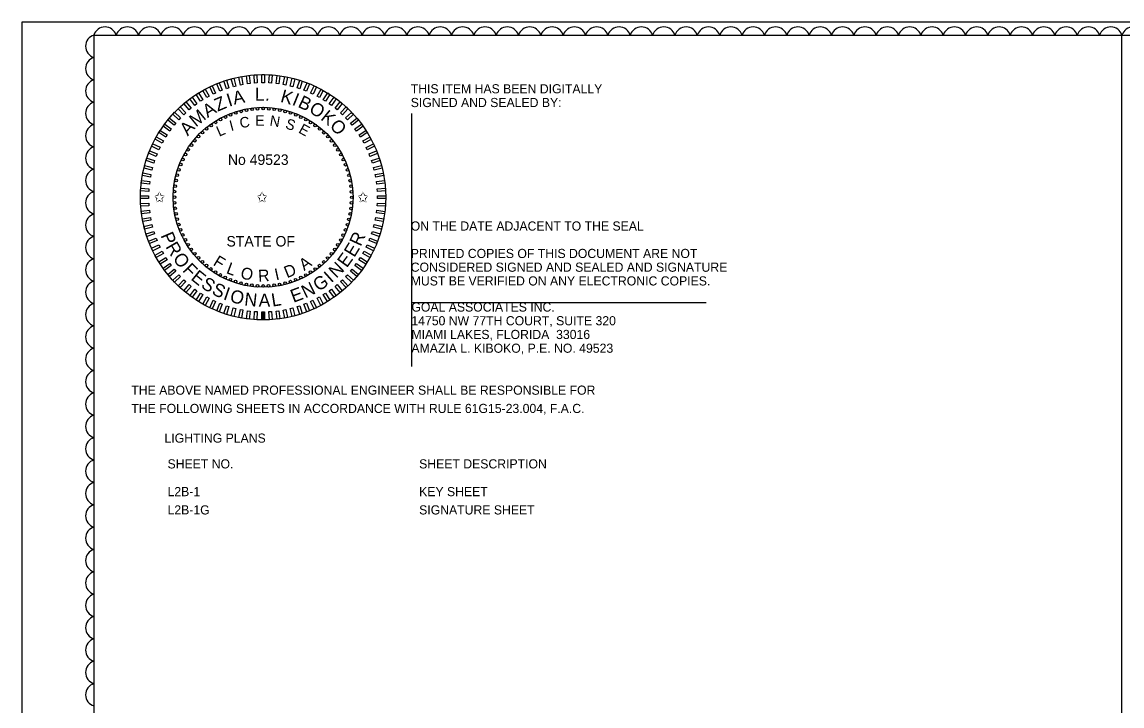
# Model space of a CAD drawing. Extents: x -816.9 to -790.1, y -2199.5 to -2188.9.
# Drawn here: x -811.34 to -802.91, y -2194.13 to -2188.9 of the extents above; entities that cross this region are included whole.
import ezdxf

# ---------------------------------------------------------------- set-up
doc = ezdxf.new("R2010")
doc.units = 0
for name, color, linetype in [('Cloud_dp', 7, 'Continuous'), ('Logo_dp', 7, 'Continuous'), ('NonPlottingEle_dp', 7, 'Continuous'), ('PlotBorder_dp', 7, 'Continuous'), ('ScratchEle_dp', 7, 'Continuous'), ('SheetBorder_dp', 7, 'Continuous'), ('TextMisc', 7, 'Continuous'), ('TextNotes', 7, 'Continuous')]:
    doc.layers.add(name, color=color, linetype=linetype)

msp = doc.modelspace()

# ---------------------------------------------------------------- linework, layer by layer
at = {"layer": 'Cloud_dp'}
for centre, start, end in [((-810.7002, -2189.0276), 17.5, 162.5), ((-810.5291, -2189.0276), 17.5, 162.5), ((-810.358, -2189.0276), 17.5, 162.5), ((-810.1868, -2189.0276), 17.5, 162.5), ((-810.0157, -2189.0276), 17.5, 162.5), ((-809.8446, -2189.0276), 17.5, 162.5), ((-809.6735, -2189.0276), 17.5, 162.5), ((-809.5024, -2189.0276), 17.5, 162.5), ((-809.3312, -2189.0276), 17.5, 162.5), ((-809.1601, -2189.0276), 17.5, 162.5), ((-808.989, -2189.0276), 17.5, 162.5), ((-808.8179, -2189.0276), 17.5, 162.5), ((-808.6467, -2189.0276), 17.5, 162.5), ((-808.4756, -2189.0276), 17.5, 162.5), ((-808.3045, -2189.0276), 17.5, 162.5), ((-808.1334, -2189.0276), 17.5, 162.5), ((-807.9622, -2189.0276), 17.5, 162.5), ((-807.7911, -2189.0276), 17.5, 162.5), ((-807.62, -2189.0276), 17.5, 162.5), ((-807.4489, -2189.0276), 17.5, 162.5), ((-807.2778, -2189.0276), 17.5, 162.5), ((-807.1066, -2189.0276), 17.5, 162.5), ((-806.9355, -2189.0276), 17.5, 162.5), ((-806.7644, -2189.0276), 17.5, 162.5), ((-806.5933, -2189.0276), 17.5, 162.5), ((-806.4221, -2189.0276), 17.5, 162.5), ((-806.251, -2189.0276), 17.5, 162.5), ((-806.0799, -2189.0276), 17.5, 162.5), ((-805.9088, -2189.0276), 17.5, 162.5), ((-805.7377, -2189.0276), 17.5, 162.5), ((-805.5665, -2189.0276), 17.5, 162.5), ((-805.3954, -2189.0276), 17.5, 162.5), ((-805.2243, -2189.0276), 17.5, 162.5), ((-805.0532, -2189.0276), 17.5, 162.5), ((-804.882, -2189.0276), 17.5, 162.5), ((-804.7109, -2189.0276), 17.5, 162.5), ((-804.5398, -2189.0276), 17.5, 162.5), ((-804.3687, -2189.0276), 17.5, 162.5), ((-804.1976, -2189.0276), 17.5, 162.5), ((-804.0264, -2189.0276), 17.5, 162.5), ((-803.8553, -2189.0276), 17.5, 162.5), ((-803.6842, -2189.0276), 17.5, 162.5), ((-803.5131, -2189.0276), 17.5, 162.5), ((-803.3419, -2189.0276), 17.5, 162.5), ((-803.1708, -2189.0276), 17.5, 162.5), ((-802.9997, -2189.0276), 17.5, 162.5), ((-802.8286, -2189.0276), 17.5, 162.5), ((-810.7588, -2189.0862), 107.5, 252.5), ((-810.7588, -2189.2573), 107.5, 252.5), ((-810.7588, -2189.4284), 107.5, 252.5), ((-810.7588, -2189.5996), 107.5, 252.5), ((-810.7588, -2189.7707), 107.5, 252.5), ((-810.7588, -2189.9418), 107.5, 252.5), ((-810.7588, -2190.1129), 107.5, 252.5), ((-810.7588, -2190.2841), 107.5, 252.5), ((-810.7588, -2190.4552), 107.5, 252.5), ((-810.7588, -2190.6263), 107.5, 252.5), ((-810.7588, -2190.7974), 107.5, 252.5), ((-810.7588, -2190.9685), 107.5, 252.5), ((-810.7588, -2191.1397), 107.5, 252.5), ((-810.7588, -2191.3108), 107.5, 252.5), ((-810.7588, -2191.4819), 107.5, 252.5), ((-810.7588, -2191.653), 107.5, 252.5), ((-810.7588, -2191.8242), 107.5, 252.5), ((-810.7588, -2191.9953), 107.5, 252.5), ((-810.7588, -2192.1664), 107.5, 252.5), ((-810.7588, -2192.3375), 107.5, 252.5), ((-810.7588, -2192.5087), 107.5, 252.5), ((-810.7588, -2192.6798), 107.5, 252.5), ((-810.7588, -2192.8509), 107.5, 252.5), ((-810.7588, -2193.022), 107.5, 252.5), ((-810.7588, -2193.1931), 107.5, 252.5), ((-810.7588, -2193.3643), 107.5, 252.5), ((-810.7588, -2193.5354), 107.5, 252.5), ((-810.7588, -2193.7065), 107.5, 252.5), ((-810.7588, -2193.8776), 107.5, 252.5), ((-810.7588, -2194.0488), 107.5, 252.5)]:
    msp.add_arc(centre, 0.0897, start, end, dxfattribs=at)
at = {"layer": 'Logo_dp'}
for p, q in [((-809.5, -2191.1804), (-809.5002, -2191.1179)), ((-809.49, -2191.1804), (-809.4902, -2191.1178)), ((-809.48, -2191.1804), (-809.4802, -2191.1178))]:
    msp.add_line(p, q, dxfattribs=at)
for points in [[(-809.8031, -2189.4233), (-809.8219, -2189.4307), (-809.8449, -2189.3726), (-809.8261, -2189.3652)], [(-809.7511, -2189.4052), (-809.7703, -2189.4115), (-809.7896, -2189.352), (-809.7704, -2189.3458)], [(-809.698, -2189.3905), (-809.7176, -2189.3955), (-809.7332, -2189.335), (-809.7136, -2189.3299)], [(-809.6442, -2189.3791), (-809.664, -2189.3829), (-809.6758, -2189.3215), (-809.6559, -2189.3177)], [(-809.5897, -2189.3711), (-809.6098, -2189.3737), (-809.6176, -2189.3116), (-809.5976, -2189.3091)], [(-809.5349, -2189.3666), (-809.555, -2189.3679), (-809.559, -2189.3055), (-809.5388, -2189.3042)], [(-809.4798, -2189.3655), (-809.5, -2189.3655), (-809.5, -2189.303), (-809.4798, -2189.303)], [(-809.4248, -2189.3679), (-809.445, -2189.3666), (-809.4411, -2189.3042), (-809.4209, -2189.3055)], [(-809.3701, -2189.3737), (-809.3901, -2189.3712), (-809.3823, -2189.3091), (-809.3623, -2189.3117)], [(-809.3158, -2189.3829), (-809.3357, -2189.3792), (-809.324, -2189.3177), (-809.3041, -2189.3215)], [(-809.2623, -2189.3956), (-809.2818, -2189.3905), (-809.2663, -2189.33), (-809.2467, -2189.335)], [(-809.2096, -2189.4115), (-809.2288, -2189.4053), (-809.2095, -2189.3458), (-809.1903, -2189.3521)], [(-809.158, -2189.4308), (-809.1768, -2189.4234), (-809.1538, -2189.3652), (-809.135, -2189.3727)], [(-809.9509, -2189.4964), (-809.968, -2189.5073), (-810.0015, -2189.4545), (-809.9844, -2189.4437)], [(-809.9032, -2189.469), (-809.9209, -2189.4787), (-809.951, -2189.4239), (-809.9333, -2189.4142)], [(-809.8539, -2189.4446), (-809.8721, -2189.4532), (-809.8988, -2189.3966), (-809.8805, -2189.388)], [(-809.1077, -2189.4532), (-809.126, -2189.4446), (-809.0994, -2189.3881), (-809.0811, -2189.3967)], [(-809.059, -2189.4788), (-809.0767, -2189.4691), (-809.0466, -2189.4143), (-809.0289, -2189.424)], [(-809.0119, -2189.5074), (-809.029, -2189.4965), (-808.9955, -2189.4438), (-808.9784, -2189.4546)], [(-810.0407, -2189.5601), (-810.0562, -2189.573), (-810.0961, -2189.5248), (-810.0805, -2189.5119)], [(-809.9968, -2189.5268), (-810.0131, -2189.5387), (-810.0499, -2189.4881), (-810.0335, -2189.4763)], [(-808.9668, -2189.5388), (-808.9831, -2189.527), (-808.9464, -2189.4764), (-808.93, -2189.4883)], [(-808.9237, -2189.5731), (-808.9392, -2189.5602), (-808.8994, -2189.512), (-808.8838, -2189.5249)], [(-810.1217, -2189.6345), (-810.1356, -2189.6492), (-810.1812, -2189.6064), (-810.1673, -2189.5917)], [(-810.0824, -2189.596), (-810.0971, -2189.6098), (-810.1399, -2189.5643), (-810.1252, -2189.5504)], [(-808.8828, -2189.61), (-808.8975, -2189.5961), (-808.8547, -2189.5505), (-808.84, -2189.5644)], [(-808.8443, -2189.6493), (-808.8582, -2189.6346), (-808.8126, -2189.5918), (-808.7988, -2189.6065)], [(-810.1929, -2189.7184), (-810.2048, -2189.7348), (-810.2553, -2189.698), (-810.2435, -2189.6817)], [(-810.1586, -2189.6753), (-810.1715, -2189.6909), (-810.2197, -2189.6511), (-810.2068, -2189.6355)], [(-808.8084, -2189.691), (-808.8213, -2189.6755), (-808.7731, -2189.6356), (-808.7602, -2189.6512)], [(-808.7752, -2189.7349), (-808.7871, -2189.7186), (-808.7365, -2189.6818), (-808.7246, -2189.6982)], [(-810.2529, -2189.8106), (-810.2626, -2189.8284), (-810.3174, -2189.7982), (-810.3077, -2189.7805)], [(-810.2243, -2189.7636), (-810.2352, -2189.7807), (-810.288, -2189.7472), (-810.2771, -2189.7301)], [(-808.7448, -2189.7808), (-808.7556, -2189.7638), (-808.7028, -2189.7303), (-808.692, -2189.7473)], [(-808.7173, -2189.8285), (-808.7271, -2189.8108), (-808.6723, -2189.7807), (-808.6625, -2189.7984)], [(-810.2785, -2189.8594), (-810.2871, -2189.8777), (-810.3436, -2189.8511), (-810.335, -2189.8328)], [(-808.6929, -2189.8779), (-808.7015, -2189.8596), (-808.6449, -2189.8329), (-808.6363, -2189.8512)], [(-810.3202, -2189.9612), (-810.3264, -2189.9805), (-810.3859, -2189.9611), (-810.3796, -2189.9419)], [(-810.3009, -2189.9097), (-810.3084, -2189.9285), (-810.3665, -2189.9054), (-810.359, -2189.8866)], [(-808.6716, -2189.9286), (-808.6791, -2189.9098), (-808.6209, -2189.8868), (-808.6135, -2189.9056)], [(-808.6536, -2189.9806), (-808.6598, -2189.9614), (-808.6004, -2189.9421), (-808.5941, -2189.9613)], [(-810.3361, -2190.0139), (-810.3412, -2190.0335), (-810.4017, -2190.0179), (-810.3967, -2189.9984)], [(-808.6388, -2190.0337), (-808.6439, -2190.0141), (-808.5833, -2189.9985), (-808.5783, -2190.0181)], [(-810.358, -2190.1218), (-810.3605, -2190.1418), (-810.4226, -2190.134), (-810.42, -2190.1139)], [(-810.3488, -2190.0675), (-810.3526, -2190.0873), (-810.414, -2190.0756), (-810.4102, -2190.0558)], [(-808.6275, -2190.0875), (-808.6312, -2190.0677), (-808.5698, -2190.056), (-808.566, -2190.0758)], [(-808.6195, -2190.142), (-808.622, -2190.1219), (-808.56, -2190.1141), (-808.5575, -2190.1342)], [(-810.3638, -2190.1765), (-810.3651, -2190.1967), (-810.4275, -2190.1927), (-810.4262, -2190.1726)], [(-808.6149, -2190.1968), (-808.6162, -2190.1767), (-808.5538, -2190.1727), (-808.5525, -2190.1929)], [(-810.3662, -2190.2315), (-810.3662, -2190.2517), (-810.4287, -2190.2517), (-810.4287, -2190.2315)], [(-810.3651, -2190.2865), (-810.3638, -2190.3067), (-810.4262, -2190.3106), (-810.4275, -2190.2904)], [(-808.6162, -2190.3069), (-808.615, -2190.2867), (-808.5526, -2190.2906), (-808.5538, -2190.3108)], [(-808.6139, -2190.2519), (-808.6139, -2190.2317), (-808.5513, -2190.2317), (-808.5513, -2190.2519)], [(-810.3606, -2190.3414), (-810.358, -2190.3614), (-810.4201, -2190.3693), (-810.4226, -2190.3492)], [(-808.622, -2190.3616), (-808.6195, -2190.3416), (-808.5575, -2190.3494), (-808.56, -2190.3695)], [(-810.3526, -2190.3958), (-810.3488, -2190.4157), (-810.4102, -2190.4274), (-810.414, -2190.4076)], [(-810.3412, -2190.4497), (-810.3362, -2190.4693), (-810.3967, -2190.4848), (-810.4018, -2190.4652)], [(-808.6439, -2190.4695), (-808.6389, -2190.4499), (-808.5783, -2190.4654), (-808.5834, -2190.485)], [(-808.6313, -2190.4159), (-808.6275, -2190.396), (-808.5661, -2190.4077), (-808.5699, -2190.4276)], [(-810.3265, -2190.5027), (-810.3202, -2190.522), (-810.3797, -2190.5413), (-810.3859, -2190.5221)], [(-808.6599, -2190.5221), (-808.6536, -2190.5029), (-808.5942, -2190.5222), (-808.6004, -2190.5415)], [(-810.3084, -2190.5547), (-810.301, -2190.5735), (-810.3591, -2190.5966), (-810.3666, -2190.5778)], [(-810.2872, -2190.6055), (-810.2785, -2190.6238), (-810.3351, -2190.6504), (-810.3437, -2190.6321)], [(-808.7016, -2190.624), (-808.693, -2190.6057), (-808.6364, -2190.6323), (-808.645, -2190.6506)], [(-808.6791, -2190.5737), (-808.6717, -2190.5549), (-808.6136, -2190.5779), (-808.621, -2190.5967)], [(-810.2627, -2190.6548), (-810.253, -2190.6726), (-810.3078, -2190.7027), (-810.3175, -2190.685)], [(-810.2353, -2190.7026), (-810.2244, -2190.7196), (-810.2772, -2190.7531), (-810.2881, -2190.7361)], [(-808.7557, -2190.7198), (-808.7449, -2190.7027), (-808.6921, -2190.7362), (-808.7029, -2190.7533)], [(-808.7271, -2190.6727), (-808.7174, -2190.655), (-808.6626, -2190.6851), (-808.6724, -2190.7028)], [(-810.2049, -2190.7484), (-810.193, -2190.7648), (-810.2436, -2190.8015), (-810.2554, -2190.7852)], [(-810.1716, -2190.7923), (-810.1587, -2190.8079), (-810.2069, -2190.8477), (-810.2198, -2190.8322)], [(-808.8214, -2190.808), (-808.8085, -2190.7925), (-808.7604, -2190.8323), (-808.7732, -2190.8479)], [(-808.7872, -2190.7649), (-808.7753, -2190.7486), (-808.7247, -2190.7853), (-808.7366, -2190.8017)], [(-810.1357, -2190.834), (-810.1219, -2190.8488), (-810.1675, -2190.8916), (-810.1813, -2190.8768)], [(-810.0972, -2190.8734), (-810.0825, -2190.8872), (-810.1253, -2190.9328), (-810.14, -2190.919)], [(-808.8977, -2190.8874), (-808.8829, -2190.8735), (-808.8401, -2190.9191), (-808.8549, -2190.9329)], [(-808.8583, -2190.8489), (-808.8445, -2190.8342), (-808.7989, -2190.877), (-808.8127, -2190.8917)], [(-810.0564, -2190.9103), (-810.0408, -2190.9232), (-810.0807, -2190.9713), (-810.0962, -2190.9585)], [(-810.0133, -2190.9445), (-809.9969, -2190.9564), (-810.0337, -2191.007), (-810.05, -2190.9951)], [(-808.9833, -2190.9565), (-808.9669, -2190.9446), (-808.9302, -2190.9952), (-808.9465, -2191.0071)], [(-808.9394, -2190.9233), (-808.9238, -2190.9104), (-808.884, -2190.9586), (-808.8995, -2190.9715)], [(-809.9681, -2190.976), (-809.951, -2190.9868), (-809.9845, -2191.0396), (-810.0016, -2191.0288)], [(-809.9211, -2191.0046), (-809.9034, -2191.0143), (-809.9335, -2191.0691), (-809.9512, -2191.0594)], [(-809.8723, -2191.0301), (-809.854, -2191.0387), (-809.8806, -2191.0953), (-809.8989, -2191.0867)], [(-809.822, -2191.0526), (-809.8033, -2191.06), (-809.8263, -2191.1181), (-809.8451, -2191.1107)], [(-809.177, -2191.0601), (-809.1582, -2191.0526), (-809.1352, -2191.1108), (-809.154, -2191.1182)], [(-809.1262, -2191.0388), (-809.1079, -2191.0302), (-809.0813, -2191.0868), (-809.0996, -2191.0954)], [(-809.0769, -2191.0144), (-809.0592, -2191.0047), (-809.029, -2191.0594), (-809.0467, -2191.0692)], [(-809.0292, -2190.9869), (-809.0121, -2190.9761), (-808.9786, -2191.0289), (-808.9957, -2191.0397)], [(-809.7705, -2191.0718), (-809.7513, -2191.0781), (-809.7706, -2191.1375), (-809.7898, -2191.1313)], [(-809.7178, -2191.0878), (-809.6982, -2191.0928), (-809.7138, -2191.1534), (-809.7333, -2191.1484)], [(-809.6642, -2191.1004), (-809.6444, -2191.1042), (-809.6561, -2191.1656), (-809.6759, -2191.1618)], [(-809.61, -2191.1097), (-809.5899, -2191.1122), (-809.5977, -2191.1742), (-809.6178, -2191.1717)], [(-809.5552, -2191.1155), (-809.535, -2191.1168), (-809.539, -2191.1792), (-809.5591, -2191.1779)], [(-809.5002, -2191.1179), (-809.48, -2191.1179), (-809.48, -2191.1804), (-809.5002, -2191.1804)], [(-809.4452, -2191.1168), (-809.425, -2191.1155), (-809.4211, -2191.1779), (-809.4413, -2191.1792)], [(-809.3903, -2191.1122), (-809.3703, -2191.1097), (-809.3624, -2191.1717), (-809.3825, -2191.1743)], [(-809.3359, -2191.1043), (-809.316, -2191.1005), (-809.3043, -2191.1619), (-809.3241, -2191.1657)], [(-809.282, -2191.0929), (-809.2624, -2191.0878), (-809.2469, -2191.1484), (-809.2665, -2191.1534)], [(-809.229, -2191.0781), (-809.2097, -2191.0719), (-809.1904, -2191.1313), (-809.2097, -2191.1376)]]:
    msp.add_lwpolyline(points, close=True, dxfattribs=at)
for centre in [(-809.7783, -2189.6277), (-809.7392, -2189.6108), (-809.6991, -2189.5964), (-809.6582, -2189.5845), (-809.6166, -2189.5752), (-809.5745, -2189.5686), (-809.5321, -2189.5646), (-809.4895, -2189.5633), (-809.4469, -2189.5647), (-809.4044, -2189.5687), (-809.3624, -2189.5755), (-809.3208, -2189.5848), (-809.2799, -2189.5967), (-809.2398, -2189.6112), (-809.2007, -2189.6281), (-809.922, -2189.7186), (-809.8883, -2189.6926), (-809.853, -2189.6686), (-809.8163, -2189.647), (-809.1627, -2189.6475), (-809.1261, -2189.6692), (-809.0908, -2189.6932), (-809.9841, -2189.7769), (-809.954, -2189.7468), (-809.0572, -2189.7194), (-809.0252, -2189.7476), (-808.9951, -2189.7777), (-810.0625, -2189.8777), (-810.0385, -2189.8425), (-810.0123, -2189.8088), (-808.967, -2189.8097), (-808.9409, -2189.8434), (-808.917, -2189.8787), (-810.1036, -2189.9523), (-810.0842, -2189.9144), (-808.8953, -2189.9154), (-808.876, -2189.9534), (-810.135, -2190.0315), (-810.1205, -2189.9914), (-808.8591, -2189.9925), (-808.8447, -2190.0326), (-810.1563, -2190.114), (-810.1469, -2190.0724), (-808.8328, -2190.0735), (-808.8236, -2190.1151), (-810.167, -2190.1985), (-810.163, -2190.1561), (-808.8169, -2190.1572), (-808.813, -2190.1997), (-810.1684, -2190.2411), (-810.1671, -2190.2837), (-808.813, -2190.2848), (-808.8117, -2190.2422), (-810.1631, -2190.3261), (-810.1565, -2190.3682), (-808.8238, -2190.3693), (-808.8171, -2190.3273), (-810.1472, -2190.4098), (-810.1354, -2190.4508), (-808.845, -2190.4518), (-808.8331, -2190.4109), (-810.121, -2190.4909), (-810.1041, -2190.53), (-808.8765, -2190.531), (-808.8595, -2190.4919), (-810.0847, -2190.568), (-810.0631, -2190.6047), (-810.0392, -2190.64), (-808.9416, -2190.6409), (-808.9176, -2190.6056), (-808.8959, -2190.569), (-810.0131, -2190.6736), (-809.9849, -2190.7056), (-808.9959, -2190.7065), (-808.9677, -2190.6745), (-809.9548, -2190.7358), (-809.9229, -2190.764), (-809.8892, -2190.7902), (-809.0918, -2190.7908), (-809.0581, -2190.7647), (-809.0261, -2190.7366), (-809.854, -2190.8141), (-809.8173, -2190.8359), (-809.7794, -2190.8552), (-809.7403, -2190.8722), (-809.7002, -2190.8867), (-809.2809, -2190.887), (-809.2408, -2190.8726), (-809.2017, -2190.8557), (-809.1637, -2190.8364), (-809.127, -2190.8147), (-809.6593, -2190.8986), (-809.6177, -2190.9079), (-809.5756, -2190.9146), (-809.5332, -2190.9187), (-809.49, -2190.9201), (-809.448, -2190.9187), (-809.4056, -2190.9148), (-809.3635, -2190.9081), (-809.3219, -2190.8989)]:
    msp.add_circle(centre, 0.01, dxfattribs=at)
at = {"layer": 'NonPlottingEle_dp'}
for radius in [0.9387, 0.6884]:
    msp.add_circle((-809.49, -2190.2417), radius, dxfattribs=at)
at = {"layer": 'PlotBorder_dp'}
msp.add_lwpolyline([(-811.3358, -2199.5006), (-794.8358, -2199.5006), (-794.8358, -2188.9006), (-811.3358, -2188.9006)], close=True, dxfattribs=at)
at = {"layer": 'ScratchEle_dp'}
for p, q in [((-808.3546, -2189.6017), (-808.3546, -2191.5365)), ((-808.3546, -2191.0465), (-806.0979, -2191.0465))]:
    msp.add_line(p, q, dxfattribs=at)
at = {"layer": 'SheetBorder_dp'}
for p, q in [((-810.7858, -2189.0006), (-810.7858, -2199.4006)), ((-810.7858, -2189.0006), (-795.3858, -2189.0006)), ((-802.9152, -2198.6006), (-802.9152, -2189.0006))]:
    msp.add_line(p, q, dxfattribs=at)

# ---------------------------------------------------------------- texts
at = {"layer": 'Logo_dp'}
for s, rotation, p in [('C', 8.98261, (-809.6632, -2189.7131)), ('E', 359.96623, (-809.5504, -2189.6942)), ('N', 350.64643, (-809.4434, -2189.6927)), ('L', 23.30524, (-809.8266, -2189.7788)), ('I', 14.81888, (-809.7359, -2189.7358)), ('S', 341.03996, (-809.3261, -2189.7116)), ('E', 331.16864, (-809.2245, -2189.7442))]:
    msp.add_text(s, height=0.0801, rotation=rotation, dxfattribs=at).set_placement(p)
for p in [(-810.3261, -2190.2797), (-809.5404, -2190.2797), (-808.7675, -2190.2797)]:
    msp.add_text('✩', height=0.0801, dxfattribs=at).set_placement(p)
at = {"layer": 'TextMisc'}
for s, height, rotation, p in [('I', 0.1001, 17.68363, (-809.7505, -2189.5498)), ('A', 0.1001, 11.91844, (-809.7111, -2189.5338)), ('L', 0.1001, 359.96623, (-809.5537, -2189.5034)), ('K', 0.1001, 344.27273, (-809.3628, -2189.5106)), ('I', 0.1001, 337.77772, (-809.2741, -2189.5325)), ('A', 0.1001, 31.46601, (-809.9149, -2189.6362)), ('Z', 0.1001, 23.30524, (-809.8374, -2189.5875)), ('.', 0.1001, 353.78581, (-809.4769, -2189.5005)), ('B', 0.1001, 334.48695, (-809.23, -2189.5478)), ('O', 0.1001, 327.82385, (-809.1453, -2189.5865)), ('M', 0.1001, 39.30005, (-810.0041, -2189.7084)), ('K', 0.1001, 321.0594, (-809.0556, -2189.6437)), ('A', 0.1001, 46.80938, (-810.0664, -2189.777)), ('O', 0.1001, 314.20329, (-808.9858, -2189.7014)), ('P', 0.1002, 293.19548, (-810.2767, -2190.5336)), ('R', 0.1002, 65.28865, (-808.7427, -2190.6231)), ('R', 0.1002, 300.25949, (-810.2398, -2190.6197)), ('E', 0.1002, 58.61694, (-808.7919, -2190.7072)), ('O', 0.1002, 307.26617, (-810.1856, -2190.7116)), ('F', 0.0902, 328.53399, (-809.879, -2190.7577)), ('A', 0.0902, 35.54629, (-809.1752, -2190.807)), ('E', 0.1002, 53.99864, (-808.8492, -2190.786)), ('F', 0.1002, 314.20329, (-810.1121, -2190.8042)), ('E', 0.1002, 321.0594, (-810.0487, -2190.8679)), ('L', 0.0902, 339.48752, (-809.7776, -2190.8207)), ('O', 0.0902, 348.08156, (-809.668, -2190.8614)), ('R', 0.0902, 3.10738, (-809.5257, -2190.8876)), ('I', 0.0902, 12.52485, (-809.3913, -2190.8785)), ('D', 0.0902, 22.22228, (-809.3071, -2190.8616)), ('N', 0.1002, 44.34211, (-808.9294, -2190.866)), ('S', 0.1002, 327.82385, (-809.9723, -2190.9285)), ('G', 0.1002, 34.11362, (-809.0651, -2190.9664)), ('I', 0.1002, 41.83906, (-808.9688, -2190.9003)), ('S', 0.1002, 334.48695, (-809.8891, -2190.98)), ('I', 0.1002, 341.03996, (-809.8004, -2191.0213)), ('O', 0.1002, 344.27273, (-809.7512, -2191.0389)), ('N', 0.1002, 353.78581, (-809.6367, -2191.0689)), ('E', 0.1002, 20.51248, (-809.2581, -2191.0499)), ('N', 0.1002, 26.0618, (-809.1664, -2191.0166)), ('A', 0.1002, 359.96623, (-809.5242, -2191.0799)), ('L', 0.1002, 8.98261, (-809.4185, -2191.079))]:
    msp.add_text(s, height=height, rotation=rotation, dxfattribs=at).set_placement(p)
for s, height, p in [('THIS ITEM HAS BEEN DIGITALLY', 0.07, (-808.3596, -2189.4466)), ('SIGNED AND SEALED BY:', 0.07, (-808.3596, -2189.5516)), ('No 49523', 0.0801, (-809.7593, -2189.9941)), ('ON THE DATE ADJACENT TO THE SEAL', 0.07, (-808.3596, -2190.4966)), ('STATE OF', 0.0801, (-809.7701, -2190.6184)), ('PRINTED COPIES OF THIS DOCUMENT ARE NOT ', 0.07, (-808.3596, -2190.7066)), ('CONSIDERED SIGNED AND SEALED AND SIGNATURE ', 0.07, (-808.3596, -2190.8116)), ('MUST BE VERIFIED ON ANY ELECTRONIC COPIES.', 0.07, (-808.3596, -2190.9166)), ('GOAL ASSOCIATES INC.', 0.07, (-808.3546, -2191.1165)), ('14750 NW 77TH COURT, SUITE 320', 0.07, (-808.3546, -2191.2215)), ('MIAMI LAKES, FLORIDA  33016', 0.07, (-808.3546, -2191.3265)), ('AMAZIA L. KIBOKO, P.E. NO. 49523', 0.07, (-808.3546, -2191.4315)), ('THE ABOVE NAMED PROFESSIONAL ENGINEER SHALL BE RESPONSIBLE FOR ', 0.07, (-810.4987, -2191.7526)), ('THE FOLLOWING SHEETS IN ACCORDANCE WITH RULE 61G15-23.004, F.A.C.', 0.07, (-810.4987, -2191.8926)), ('LIGHTING PLANS', 0.07, (-810.245, -2192.1196))]:
    msp.add_text(s, height=height, dxfattribs=at).set_placement(p)
at = {"layer": 'TextNotes'}
for s, p in [('SHEET NO.', (-810.2215, -2192.3166)), ('SHEET DESCRIPTION', (-808.2953, -2192.3166)), ('L2B-1', (-810.2215, -2192.5288)), ('KEY SHEET', (-808.2953, -2192.5288)), ('L2B-1G', (-810.2215, -2192.6688)), ('SIGNATURE SHEET', (-808.2953, -2192.6688))]:
    msp.add_text(s, height=0.07, dxfattribs=at).set_placement(p)

doc.saveas('drawing.dxf')
